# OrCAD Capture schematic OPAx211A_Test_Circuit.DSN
size A; title: OPAx211 1.1-nv/vHz Noise, Low Power, Precision Operational; rev: 1.4; note: Datasheet: SBOS377L  EVM: N/A
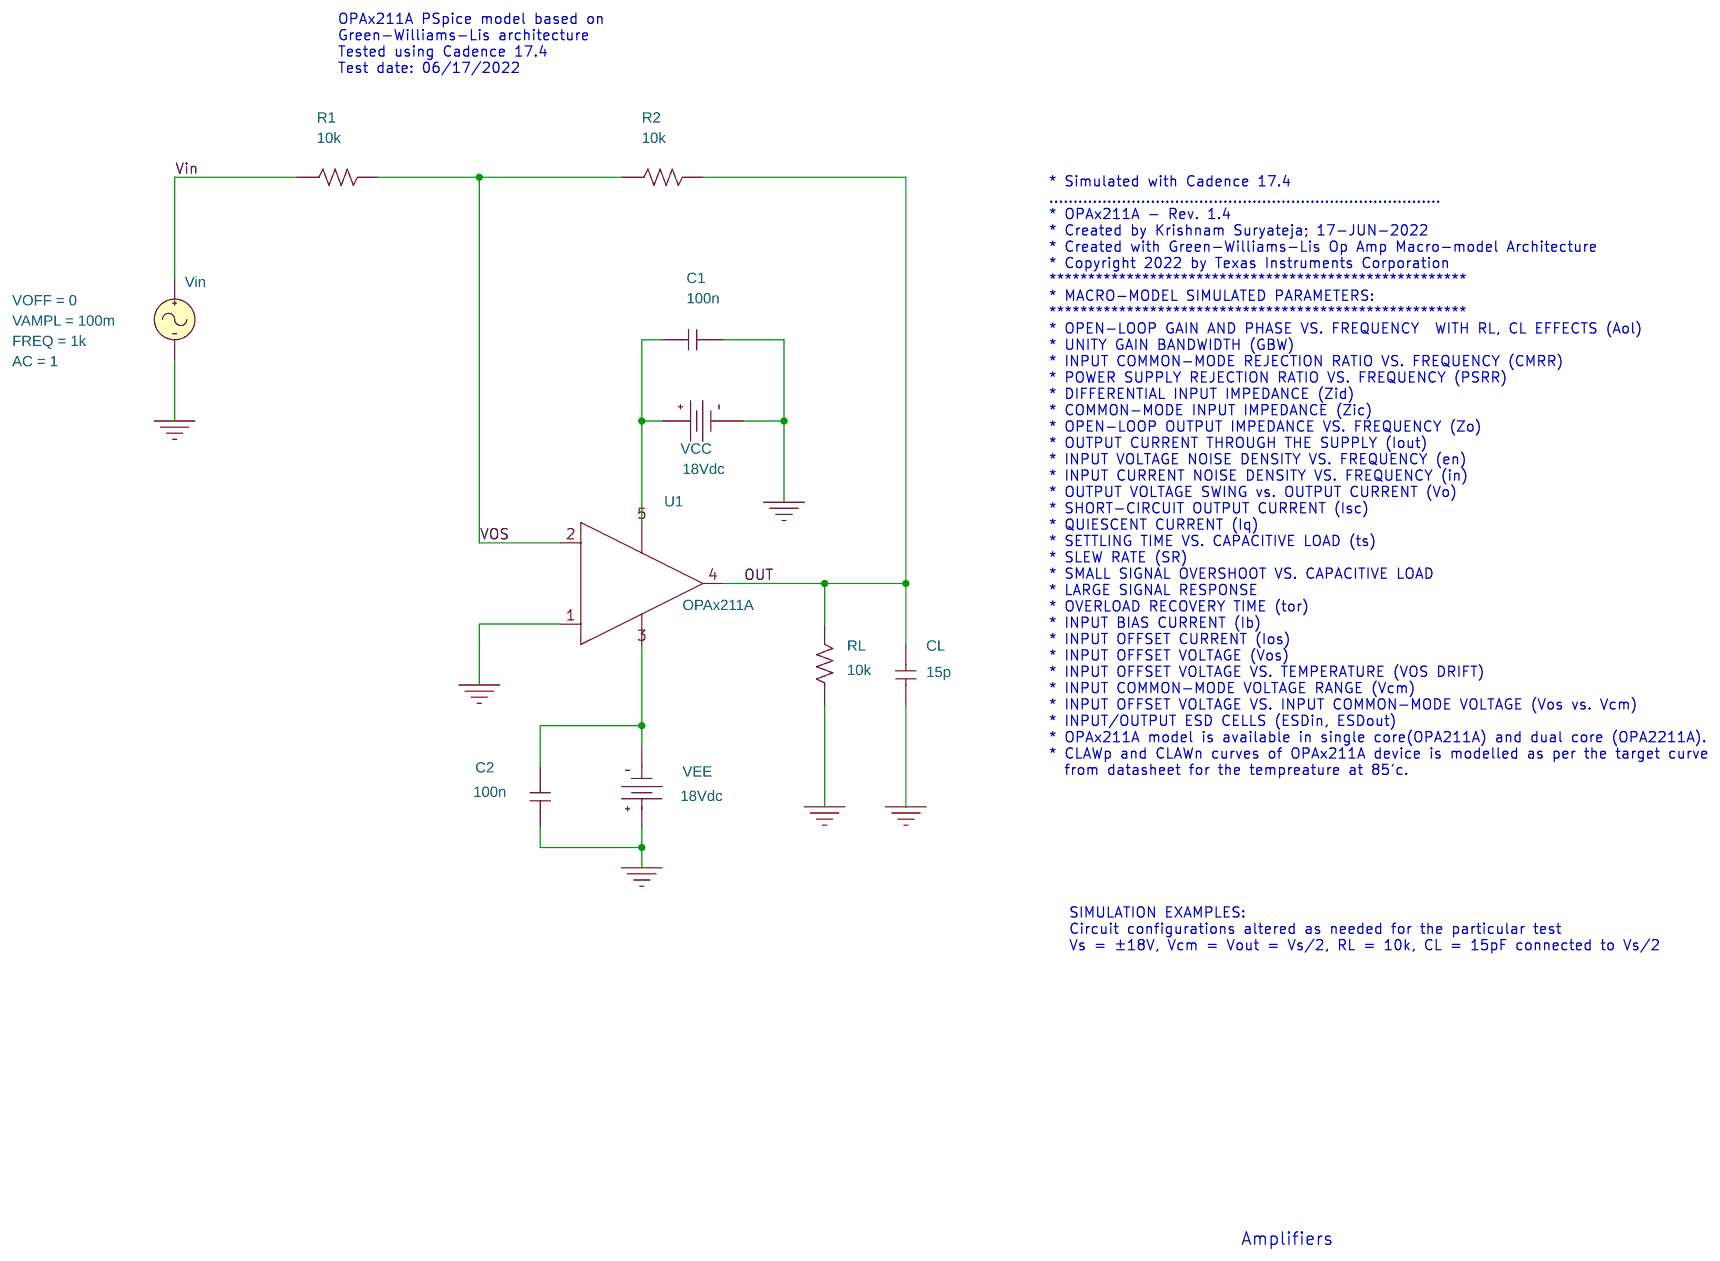
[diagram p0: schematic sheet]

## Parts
C1  100n  [cap196]
C2  100n  [cap196]
CL  15p  [cap196]
R1  10k  [AXRC05]
R2  10k  [AXRC05]
RL  10k  [AXRC05]
U1  OPAx211A
VCC  VDC
VEE  VDC
Vin  VSIN

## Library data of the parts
C1 C2 CL = C
R1 R2 RL = R
U1 = OPAx211A
VCC VEE = VDC: DC: 18Vdc
Vin = VSIN: AC: 1; FREQ: 1k; VAMPL: 100m; VOFF: 0

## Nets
Vin: R1.1 Vin.1(+)
0: C1.2 C2.1 CL.2 RL.1 U1.1(+) VCC.1(-) VEE.0(+) Vin.2(-)
OUT: CL.1 R2.2 RL.2 U1.4(OUT)
VOS: R1.2 R2.1 U1.2(-)
N27303: C1.1 U1.5(V+) VCC.0(+)
N27354: C2.2 U1.3(V-) VEE.1(-)

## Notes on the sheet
- OPAx211A PSpice model based on
  Green-Williams-Lis architecture
  Tested using Cadence 17.4
  Test date: 06/17/2022
- * Simulated with Cadence 17.4
  .................................................................................
  * OPAx211A - Rev. 1.4
  * Created by Krishnam Suryateja; 17-JUN-2022
  * Created with Green-Williams-Lis Op Amp Macro-model Architecture
  * Copyright 2022 by Texas Instruments Corporation
  ******************************************************
  * MACRO-MODEL SIMULATED PARAMETERS:
  ******************************************************
  * OPEN-LOOP GAIN AND PHASE VS. FREQUENCY  WITH RL, CL EFFECTS (Aol)
  * UNITY GAIN BANDWIDTH (GBW)
  * INPUT COMMON-MODE REJECTION RATIO VS. FREQUENCY (CMRR)
  * POWER SUPPLY REJECTION RATIO VS. FREQUENCY (PSRR)
  * DIFFERENTIAL INPUT IMPEDANCE (Zid)
  * COMMON-MODE INPUT IMPEDANCE (Zic)
  * OPEN-LOOP OUTPUT IMPEDANCE VS. FREQUENCY (Zo)
  * OUTPUT CURRENT THROUGH THE SUPPLY (Iout)
  * INPUT VOLTAGE NOISE DENSITY VS. FREQUENCY (en)
  * INPUT CURRENT NOISE DENSITY VS. FREQUENCY (in)
  * OUTPUT VOLTAGE SWING vs. OUTPUT CURRENT (Vo)
  * SHORT-CIRCUIT OUTPUT CURRENT (Isc)
  * QUIESCENT CURRENT (Iq)
  * SETTLING TIME VS. CAPACITIVE LOAD (ts)
  * SLEW RATE (SR)
  * SMALL SIGNAL OVERSHOOT VS. CAPACITIVE LOAD
  * LARGE SIGNAL RESPONSE
  * OVERLOAD RECOVERY TIME (tor)
  * INPUT BIAS CURRENT (Ib)
  * INPUT OFFSET CURRENT (Ios)
  * INPUT OFFSET VOLTAGE (Vos)
  * INPUT OFFSET VOLTAGE VS. TEMPERATURE (VOS DRIFT)
  * INPUT COMMON-MODE VOLTAGE RANGE (Vcm)
  * INPUT OFFSET VOLTAGE VS. INPUT COMMON-MODE VOLTAGE (Vos vs. Vcm)
  * INPUT/OUTPUT ESD CELLS (ESDin, ESDout)
  * OPAx211A model is available in single core(OPA211A) and dual core (OPA2211A).
  * CLAWp and CLAWn curves of OPAx211A device is modelled as per the target curve
    from datasheet for the tempreature at 85'c.
- SIMULATION EXAMPLES:
  Circuit configurations altered as needed for the particular test
  Vs = ±18V, Vcm = Vout = Vs/2, RL = 10k, CL = 15pF connected to Vs/2
- Amplifiers
